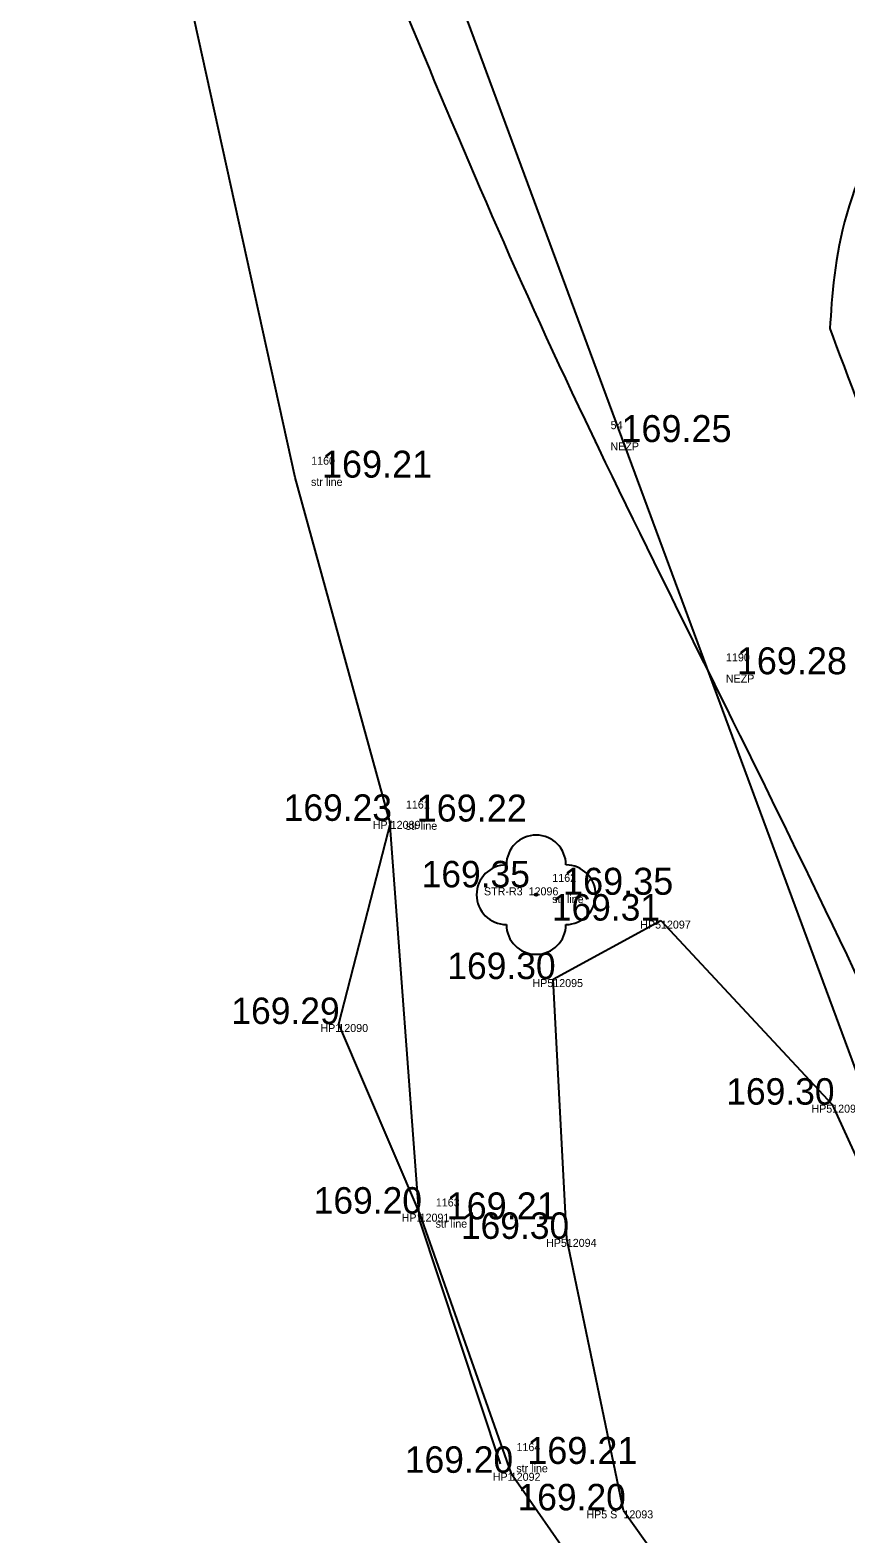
# Model space of a CAD drawing. Extents: x -566117 to -565580, y -1202428 to -1201938.
# Drawn here: x -566012.72 to -565999.47, y -1202253.46 to -1202229.03 of the extents above; entities that cross this region are included whole.
import ezdxf

# ---------------------------------------------------------------- set-up
doc = ezdxf.new("R2010")
doc.units = 0
for name, color, linetype in [('Bod', 7, 'Continuous'), ('Implicitní', 7, 'Continuous'), ('Katastr', 7, 'Continuous'), ('Kod', 7, 'Continuous'), ('Výška', 7, 'Continuous'), ('ZELEŇ', 7, 'Continuous'), ('Zpevněné plohy', 7, 'Continuous'), ('Číslo', 7, 'Continuous')]:
    doc.layers.add(name, color=color, linetype=linetype)

# ---------------------------------------------------------------- blocks, each defined once
blk = doc.blocks.new('A$C69D74C1E')
at = {"layer": 'Katastr'}
blk.add_line((111.46, -301.47), (11.33, -30.63), dxfattribs=at)
blk = doc.blocks.new('POINT_DISPLAY')
at = {"layer": 'Implicitní'}
blk.add_line((0, 0), (0, 0), dxfattribs=at)
blk = doc.blocks.new('3$13')
at = {"layer": 'ZELEŇ'}
blk.add_circle((0, 0), 0.02, dxfattribs=at)
for centre, start, end in [((0.000055, 0.484), 0, 179.9999972), ((-0.483945, 0), 90, 269.9999972), ((0.484055, 0), 270, 89.9999972), ((0.000055, -0.484), 180.0000028, 0)]:
    blk.add_arc(centre, 0.484, start, end, dxfattribs=at)
blk.add_blockref('POINT_DISPLAY', (0, 0), dxfattribs=at)

msp = doc.modelspace()

# ---------------------------------------------------------------- linework, layer by layer
at = {"layer": 'ZELEŇ'}
for p, q in [((-566006.86, -1202241.88), (-566007.71, -1202245.18)), ((-566004.22, -1202244.45), (-566002.47, -1202243.5)), ((-566002.47, -1202243.5), (-565999.69, -1202246.49)), ((-566004, -1202248.67), (-566004.22, -1202244.45)), ((-566007.71, -1202245.18), (-566006.39, -1202248.26)), ((-565999.69, -1202246.49), (-565994.22, -1202258.5)), ((-566006.39, -1202248.26), (-566004.91, -1202252.47)), ((-566003.08, -1202253.08), (-566004, -1202248.67)), ((-566004.91, -1202252.47), (-566002.37, -1202256.12)), ((-566003.08, -1202253.08), (-566000.78, -1202256.3))]:
    msp.add_line(p, q, dxfattribs=at)
msp.add_lwpolyline([(-566005.079, -1202252.326), (-566006.39, -1202248.353), (-566006.876, -1202241.891), (-566008.413, -1202236.305), (-566010.701, -1202225.895), (-566018.319, -1202206.339), (-566024.426, -1202183.871), (-566030.46, -1202163.29), (-566035.732, -1202146.225), (-566041.549, -1202133.247), (-566045.071, -1202124.917), (-566049.954, -1202117.429)], dxfattribs=at)
at = {"layer": 'Zpevněné plohy'}
for points in [[(-565996.343, -1202250.678), (-565998.087, -1202246.935), (-566000.423, -1202241.92), (-566004.309, -1202234.328), (-566007.075, -1202227.602), (-566010.343, -1202219.887), (-566012.893, -1202211.917), (-566015.796, -1202204.301), (-566017.921, -1202196.368), (-566020.346, -1202187.744), (-566022.925, -1202178.898), (-566025.07, -1202169.591), (-566028.365, -1202159.949), (-566030.289, -1202151.119), (-566033.484, -1202142.933), (-566036.408, -1202135.565), (-566040.083, -1202126.773), (-566044.556, -1202117.939), (-566046.435, -1202111.858), (-566047.33, -1202108.96)], [(-565994.381, -1202226.988), (-565994.955, -1202227.408), (-565996.366, -1202228.442), (-565998.546, -1202229.851), (-565999.611, -1202232.064), (-565999.694, -1202233.365), (-565999.727, -1202233.885)], [(-565999.727, -1202233.885), (-565999.171, -1202235.372), (-565997.108, -1202240.89), (-565993.993, -1202246.49), (-565992.01, -1202250.859), (-565991.805, -1202251.31)]]:
    msp.add_open_spline(points, degree=3, dxfattribs=at)

# ---------------------------------------------------------------- block references
at = {"layer": 'Bod'}
for p in [(-565999.547, -1202232.338), (-565999.727, -1202233.885), (-566003.551, -1202235.727), (-566008.413, -1202236.305), (-566001.677, -1202239.499), (-566006.876, -1202241.891), (-566006.86, -1202241.88), (-566004.62, -1202242.96), (-566004.497, -1202243.08), (-566002.47, -1202243.5), (-566004.22, -1202244.45), (-566007.71, -1202245.18), (-565999.69, -1202246.49), (-566006.39, -1202248.26), (-566006.39, -1202248.353), (-566004, -1202248.67), (-566005.079, -1202252.326), (-566004.91, -1202252.47), (-566003.08, -1202253.08)]:
    msp.add_blockref('POINT_DISPLAY', p, dxfattribs=at)
at = {"layer": 'Implicitní'}
msp.add_blockref('A$C69D74C1E', (-566064.93, -1202068.44), dxfattribs=at)
at = {"layer": 'ZELEŇ'}
msp.add_blockref('3$13', (-566004.497, -1202243.08), dxfattribs=at)

# ---------------------------------------------------------------- texts
at = {"layer": 'Kod'}
for s, p in [('NEZP', (-566003.291, -1202235.862)), ('str line', (-566008.154, -1202236.439)), ('NEZP', (-566001.417, -1202239.633)), ('HP1', (-566007.152, -1202242.01)), ('str line', (-566006.616, -1202242.025)), ('STR-R3', (-566005.345, -1202243.09)), ('str line', (-566004.238, -1202243.215)), ('HP5', (-566002.807, -1202243.63)), ('HP5', (-566004.557, -1202244.58)), ('HP1', (-566008.002, -1202245.31)), ('HP5', (-566000.027, -1202246.62)), ('HP1', (-566006.682, -1202248.39)), ('str line', (-566006.13, -1202248.488)), ('HP5', (-566004.337, -1202248.8)), ('str line', (-566004.82, -1202252.461)), ('HP1', (-566005.202, -1202252.6)), ('HP5 S', (-566003.682, -1202253.21))]:
    msp.add_text(s, height=0.13, dxfattribs=at).set_placement(p)
at = {"layer": 'Výška'}
for s, height, p in [('169.25', 0.4375, (-566003.113, -1202235.727)), ('169.21', 0.4375, (-566007.976, -1202236.305)), ('169.28', 0.4375, (-566001.239, -1202239.499)), ('169.23 ', 0.43, (-566008.597, -1202241.88)), ('169.22', 0.4375, (-566006.438, -1202241.891)), ('169.35 ', 0.43, (-566006.357, -1202242.96)), ('169.35', 0.4375, (-566004.06, -1202243.08)), ('169.31 ', 0.43, (-566004.243, -1202243.5)), ('169.30 ', 0.43, (-566005.94, -1202244.45)), ('169.29 ', 0.43, (-566009.447, -1202245.18)), ('169.30 ', 0.43, (-566001.41, -1202246.49)), ('169.20 ', 0.43, (-566008.11, -1202248.26)), ('169.21', 0.4375, (-566005.952, -1202248.353)), ('169.30 ', 0.43, (-566005.72, -1202248.67)), ('169.20 ', 0.43, (-566006.63, -1202252.47)), ('169.21', 0.4375, (-566004.642, -1202252.326)), ('169.20 ', 0.43, (-566004.8, -1202253.08))]:
    msp.add_text(s, height=height, dxfattribs=at).set_placement(p)
at = {"layer": 'Číslo'}
for s, p in [('54', (-566003.288, -1202235.518)), ('1160', (-566008.151, -1202236.095)), ('1190', (-566001.414, -1202239.289)), ('1161', (-566006.613, -1202241.681)), ('12089', (-566006.86, -1202242.01)), ('1162', (-566004.235, -1202242.871)), ('12096', (-566004.62, -1202243.09)), ('12097', (-566002.47, -1202243.63)), ('12095', (-566004.22, -1202244.58)), ('12090', (-566007.71, -1202245.31)), ('12098', (-565999.69, -1202246.62)), ('1163', (-566006.127, -1202248.144)), ('12091', (-566006.39, -1202248.39)), ('12094', (-566004, -1202248.8)), ('1164', (-566004.817, -1202252.117)), ('12092', (-566004.91, -1202252.6)), ('12093', (-566003.08, -1202253.21))]:
    msp.add_text(s, height=0.13, dxfattribs=at).set_placement(p)

doc.saveas('drawing.dxf')
